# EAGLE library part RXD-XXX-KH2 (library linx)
KH2 SERIES RECEIVER / DECODER Source: http://www.linxtechnologies.com .. RXD-xxx-KH2_Data_Guide.pdf
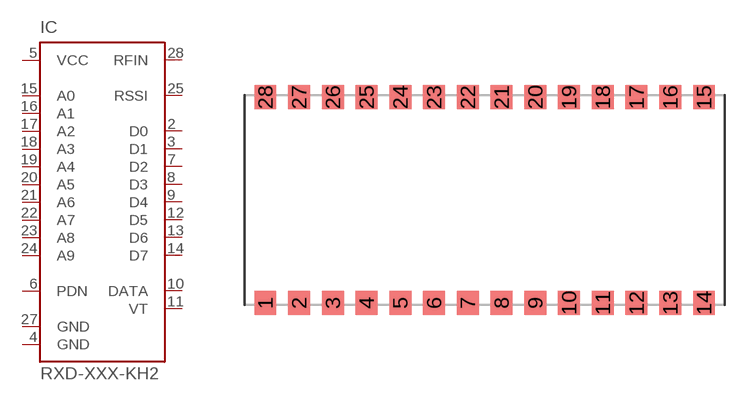
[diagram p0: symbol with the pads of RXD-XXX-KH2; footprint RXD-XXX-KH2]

Designator prefix IC

## RXD-XXX-KH2  [RXD-XXX-KH2]
2  D0
3  D1
4  GND  pwr
5  VCC  pwr
6  PDN  in
7  D2
8  D3
9  D4
10  DATA  out
11  VT  out
12  D5
13  D6
14  D7
15  A0  in
16  A1  in
17  A2  in
18  A3  in
19  A4  in
20  A5  in
21  A6  in
22  A7  in
23  A8  in
24  A9  in
25  RSSI  pas
27  GND  pwr
28  RFIN  in

## Footprint RXD-XXX-KH2 (pad centres in mm)
RXDxxx-KH2 Source: All Packages.pdf
smd 1.651 x 1.778: 1 -16.51,-7.747; 2 -13.97,-7.747; 3 -11.43,-7.747; 4 -8.89,-7.747; 5 -6.35,-7.747; 6 -3.81,-7.747; 7 -1.27,-7.747; 8 1.27,-7.747; 9 3.81,-7.747; 10 6.35,-7.747; 11 8.89,-7.747; 12 11.43,-7.747; 13 13.97,-7.747; 14 16.51,-7.747; 15 16.51,7.747; 16 13.97,7.747; 17 11.43,7.747; 18 8.89,7.747; 19 6.35,7.747; 20 3.81,7.747; 21 1.27,7.747; 22 -1.27,7.747; 23 -3.81,7.747; 24 -6.35,7.747; 25 -8.89,7.747; 26 -11.43,7.747; 27 -13.97,7.747; 28 -16.51,7.747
